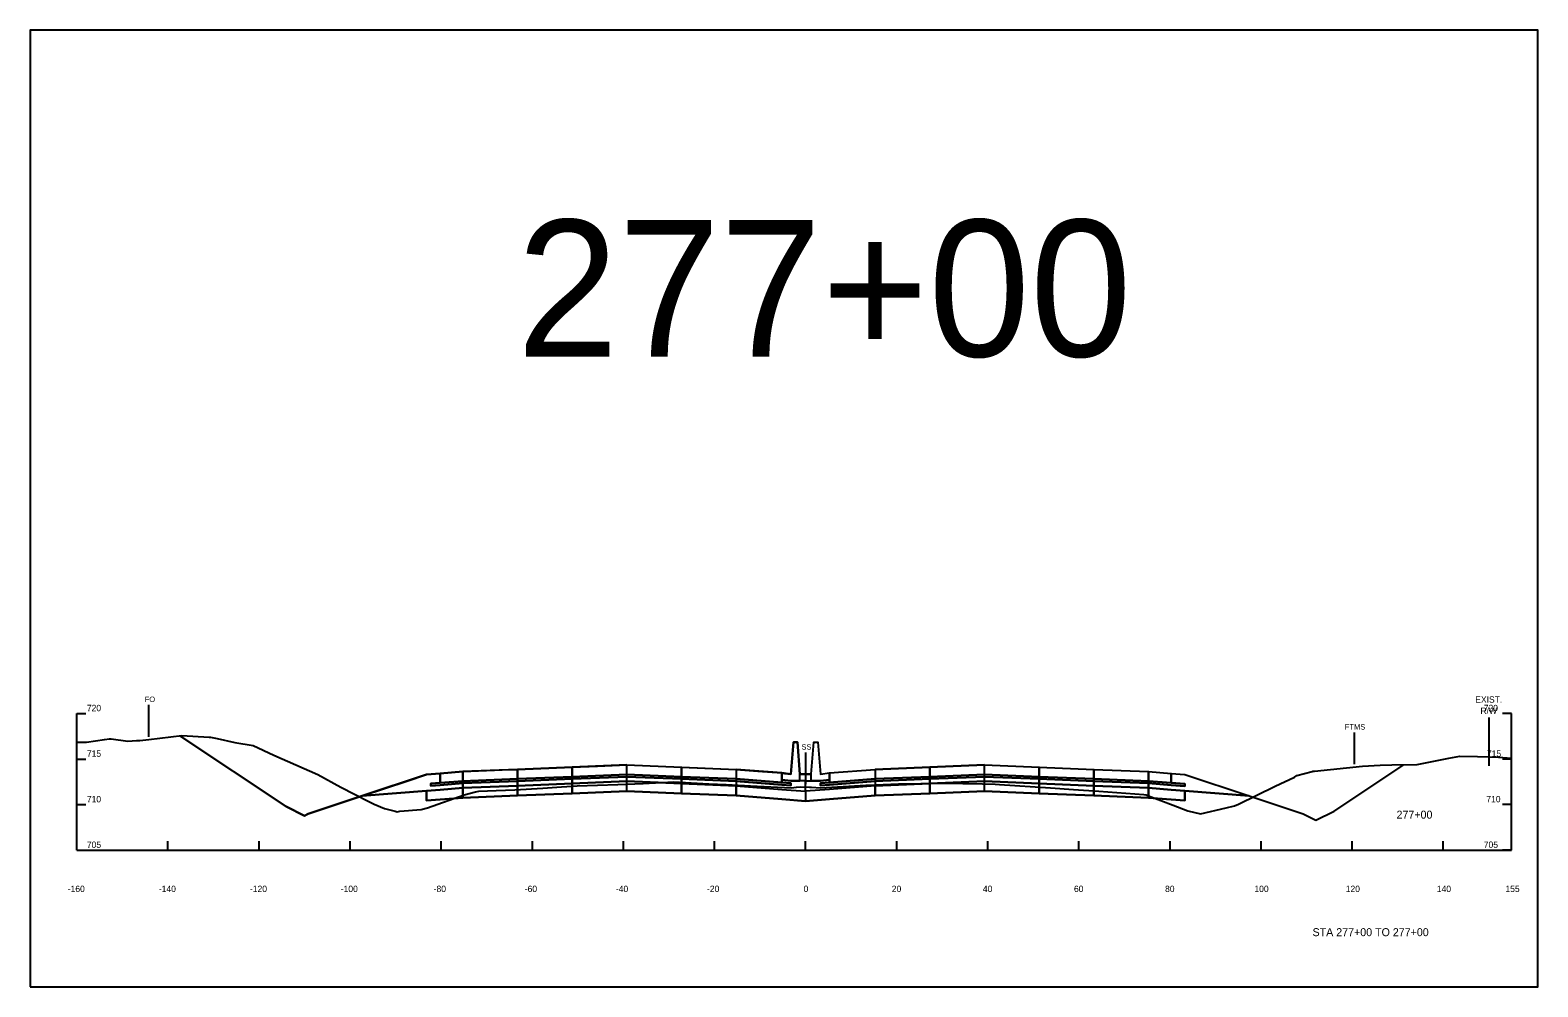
# Model space of a CAD drawing. Extents: x 0 to 2149228, y 0 to 2148913.
# Drawn here: x 2146925 to 2147256, y 2146973 to 2147183 of the extents above; entities that cross this region are included whole.
import ezdxf

# ---------------------------------------------------------------- set-up
doc = ezdxf.new("R2010")
doc.units = 0
for name, color, linetype in [('ADAMS CONST', 7, 'Continuous'), ('Default', 7, 'Continuous'), ('P_E_XS_Ground', 7, 'Continuous'), ('P_E_XS_RW', 7, 'Continuous'), ('P_E_XS_UTL', 7, 'Continuous'), ('P_MISC_TXT', 7, 'Continuous'), ('P_PROF_Grades', 7, 'Continuous'), ('P_RDWY_BarrierConc', 7, 'Continuous'), ('P_XS', 7, 'Continuous'), ('P_XS_Subgrade', 7, 'Continuous')]:
    doc.layers.add(name, color=color, linetype=linetype)

msp = doc.modelspace()

# ---------------------------------------------------------------- linework, layer by layer
at = {"layer": 'Default'}
msp.add_lwpolyline([(2146925.02, 2146973.02), (2147256.02, 2146973.02), (2147256.02, 2147183.02), (2146925.02, 2147183.02)], close=True, dxfattribs=at)
at = {"layer": 'P_E_XS_Ground'}
msp.add_lwpolyline([(2146935.27, 2147026.69), (2146937.41, 2147026.72), (2146941.32, 2147027.3), (2146942.47, 2147027.47), (2146942.82, 2147027.43), (2146946.49, 2147026.95), (2146948.37, 2147027.1), (2146949.11, 2147027.11), (2146951.07, 2147027.32), (2146958.29, 2147028.19), (2146964.35, 2147027.83), (2146964.59, 2147027.8), (2146966.04, 2147027.53), (2146969.93, 2147026.67), (2146973.99, 2147025.96), (2146978.53, 2147023.85), (2146988.17, 2147019.63), (2146993.25, 2147016.82), (2146999.38, 2147013.7), (2147000.52, 2147013.15), (2147002.84, 2147012.19), (2147005.19, 2147011.56), (2147005.59, 2147011.42), (2147006.16, 2147011.55), (2147010.86, 2147011.91), (2147012.28, 2147012.33), (2147020.33, 2147015.14), (2147022.76, 2147015.82), (2147023.55, 2147015.95), (2147027.31, 2147016.1), (2147031.4, 2147016.27), (2147037.55, 2147016.65), (2147041.69, 2147016.95), (2147045.11, 2147017.12), (2147054.06, 2147017.43), (2147059.57, 2147017.63), (2147066.31, 2147018), (2147074.01, 2147017.61), (2147077.8, 2147017.42), (2147083.2, 2147017.14), (2147092.11, 2147016.68), (2147093.25, 2147016.85), (2147094.15, 2147016.92), (2147096.11, 2147016.85), (2147096.45, 2147016.84), (2147096.58, 2147016.84), (2147098.51, 2147016.71), (2147108.5, 2147017.26), (2147112.29, 2147017.46), (2147115.66, 2147017.56), (2147125.46, 2147017.7), (2147134.11, 2147017.57), (2147136.87, 2147017.52), (2147137.84, 2147017.46), (2147149.04, 2147016.72), (2147154.06, 2147016.3), (2147159.63, 2147015.94), (2147169.51, 2147015.21), (2147170.02, 2147015.17), (2147170.51, 2147014.97), (2147175.96, 2147012.88), (2147179.21, 2147011.67), (2147181.97, 2147010.96), (2147187.56, 2147012.32), (2147189.39, 2147012.75), (2147190.28, 2147013.09), (2147198.33, 2147017.08), (2147202.56, 2147019.04), (2147203.12, 2147019.4), (2147206.45, 2147020.29), (2147206.64, 2147020.34), (2147206.97, 2147020.37), (2147217.55, 2147021.46), (2147221.42, 2147021.7), (2147223.98, 2147021.74), (2147229.52, 2147021.82), (2147236.45, 2147023.2), (2147238.9, 2147023.67), (2147242.75, 2147023.56), (2147247.41, 2147023.44), (2147250.27, 2147023.23)], dxfattribs=at)
at = {"layer": 'P_E_XS_RW'}
msp.add_line((2147245.27, 2147032.16), (2147245.27, 2147021.5), dxfattribs=at)
at = {"layer": 'P_E_XS_UTL'}
for p, q in [((2146951.09, 2147027.93), (2146951.09, 2147034.93)), ((2147215.76, 2147021.88), (2147215.76, 2147028.88)), ((2147095.29, 2147017.48), (2147095.29, 2147024.48))]:
    msp.add_line(p, q, dxfattribs=at)
at = {"layer": 'P_RDWY_BarrierConc'}
for p, q in [((2146935.27, 2147003.02), (2146935.27, 2147033.02)), ((2146935.27, 2147033.02), (2146937.27, 2147033.02)), ((2147250.27, 2147033.02), (2147248.27, 2147033.02)), ((2147250.27, 2147003.02), (2147250.27, 2147033.02)), ((2146935.27, 2147023.02), (2146937.27, 2147023.02)), ((2147250.27, 2147023.02), (2147248.27, 2147023.02)), ((2146935.27, 2147013.02), (2146937.27, 2147013.02)), ((2147250.27, 2147013.02), (2147248.27, 2147013.02)), ((2146935.27, 2147003.02), (2146935.27, 2147005.02)), ((2146935.27, 2147003.02), (2146937.27, 2147003.02)), ((2146935.27, 2147003.02), (2147250.27, 2147003.02)), ((2146955.27, 2147003.02), (2146955.27, 2147005.02)), ((2146975.27, 2147003.02), (2146975.27, 2147005.02)), ((2146995.27, 2147003.02), (2146995.27, 2147005.02)), ((2147015.27, 2147003.02), (2147015.27, 2147005.02)), ((2147035.27, 2147003.02), (2147035.27, 2147005.02)), ((2147055.27, 2147003.02), (2147055.27, 2147005.02)), ((2147075.27, 2147003.02), (2147075.27, 2147005.02)), ((2147095.27, 2147003.02), (2147095.27, 2147005.02)), ((2147115.27, 2147003.02), (2147115.27, 2147005.02)), ((2147135.27, 2147003.02), (2147135.27, 2147005.02)), ((2147155.27, 2147003.02), (2147155.27, 2147005.02)), ((2147175.27, 2147003.02), (2147175.27, 2147005.02)), ((2147195.27, 2147003.02), (2147195.27, 2147005.02)), ((2147215.27, 2147003.02), (2147215.27, 2147005.02)), ((2147235.27, 2147003.02), (2147235.27, 2147005.02)), ((2147250.27, 2147003.02), (2147248.27, 2147003.02)), ((2147250.27, 2147003.02), (2147250.27, 2147005.02))]:
    msp.add_line(p, q, dxfattribs=at)
at = {"layer": 'P_XS'}
for points in [[(2146957.91, 2147028.15), (2146981.25, 2147012.59), (2146981.38, 2147012.52), (2146985.25, 2147010.59), (2146985.63, 2147010.78), (2146986.02, 2147010.97), (2146993.32, 2147013.41), (2146997.88, 2147014.92), (2147007.71, 2147018.2), (2147012.02, 2147019.64), (2147015.02, 2147019.88), (2147020.02, 2147020.28), (2147030.4, 2147020.69), (2147032.02, 2147020.76), (2147044.02, 2147021.24), (2147049.6, 2147021.46), (2147056.02, 2147021.72), (2147068.02, 2147021.24), (2147071.5, 2147021.1), (2147080.02, 2147020.76), (2147084.74, 2147020.38), (2147090.02, 2147019.96), (2147090.65, 2147019.88), (2147092.02, 2147019.71), (2147092.58, 2147026.71), (2147093.46, 2147026.71), (2147094.02, 2147019.71), (2147095.27, 2147019.71)], [(2147095.27, 2147019.71), (2147096.52, 2147019.71), (2147097.08, 2147026.71), (2147097.96, 2147026.71), (2147098.52, 2147019.71), (2147100.52, 2147019.96), (2147110.52, 2147020.76), (2147122.52, 2147021.24), (2147134.52, 2147021.72), (2147146.52, 2147021.24), (2147158.52, 2147020.76), (2147170.52, 2147020.28), (2147175.52, 2147019.88), (2147178.52, 2147019.64), (2147192.66, 2147014.92), (2147204.52, 2147010.97), (2147207.29, 2147009.59), (2147211.29, 2147011.59), (2147226.58, 2147021.78)], [(2147095.27, 2147019.71), (2147094.02, 2147019.71), (2147095.27, 2147019.71)], [(2147095.27, 2147019.71), (2147096.52, 2147019.71), (2147095.27, 2147019.71)]]:
    msp.add_lwpolyline(points, dxfattribs=at)
for points in [[(2147094.02, 2147019.71), (2147093.46, 2147026.71), (2147092.58, 2147026.71), (2147092.02, 2147019.71), (2147090.02, 2147019.96), (2147090.02, 2147018.46), (2147092.02, 2147018.21), (2147094.02, 2147018.21)], [(2147096.52, 2147019.71), (2147097.08, 2147026.71), (2147097.96, 2147026.71), (2147098.52, 2147019.71), (2147100.52, 2147019.96), (2147100.52, 2147018.46), (2147098.52, 2147018.21), (2147096.52, 2147018.21)], [(2147056.02, 2147021.72), (2147044.02, 2147021.24), (2147044.02, 2147019.15), (2147056.02, 2147019.63)], [(2147056.02, 2147021.72), (2147068.02, 2147021.24), (2147068.02, 2147019.15), (2147056.02, 2147019.63)], [(2147134.52, 2147021.72), (2147122.52, 2147021.24), (2147122.52, 2147019.15), (2147134.52, 2147019.63)], [(2147134.52, 2147021.72), (2147146.52, 2147021.24), (2147146.52, 2147019.15), (2147134.52, 2147019.63)], [(2147020.02, 2147017.69), (2147015.02, 2147017.29), (2147013.02, 2147017.13), (2147013.02, 2147017.63), (2147015.02, 2147017.79), (2147015.02, 2147019.88), (2147012.02, 2147019.64), (2146997.88, 2147014.92), (2147012.02, 2147016.05), (2147015.02, 2147016.29), (2147020.02, 2147016.69)], [(2147020.02, 2147020.28), (2147015.02, 2147019.88), (2147015.02, 2147017.79), (2147020.02, 2147018.19)], [(2147032.02, 2147020.76), (2147020.02, 2147020.28), (2147020.02, 2147018.19), (2147032.02, 2147018.67)], [(2147032.02, 2147018.67), (2147020.02, 2147018.19), (2147020.02, 2147017.69), (2147032.02, 2147018.17)], [(2147044.02, 2147021.24), (2147032.02, 2147020.76), (2147032.02, 2147018.67), (2147044.02, 2147019.15)], [(2147044.02, 2147019.15), (2147032.02, 2147018.67), (2147032.02, 2147018.17), (2147044.02, 2147018.65)], [(2147044.02, 2147018.65), (2147032.02, 2147018.17), (2147032.02, 2147017.17), (2147044.02, 2147017.65)], [(2147056.02, 2147019.63), (2147044.02, 2147019.15), (2147044.02, 2147018.65), (2147056.02, 2147019.13)], [(2147056.02, 2147019.13), (2147044.02, 2147018.65), (2147044.02, 2147017.65), (2147056.02, 2147018.13)], [(2147056.02, 2147019.63), (2147068.02, 2147019.15), (2147068.02, 2147018.65), (2147056.02, 2147019.13)], [(2147056.02, 2147019.13), (2147068.02, 2147018.65), (2147068.02, 2147017.65), (2147056.02, 2147018.13)], [(2147068.02, 2147021.24), (2147080.02, 2147020.76), (2147080.02, 2147018.67), (2147068.02, 2147019.15)], [(2147068.02, 2147019.15), (2147080.02, 2147018.67), (2147080.02, 2147018.17), (2147068.02, 2147018.65)], [(2147068.02, 2147018.65), (2147080.02, 2147018.17), (2147080.02, 2147017.17), (2147068.02, 2147017.65)], [(2147090.02, 2147017.87), (2147090.02, 2147019.96), (2147080.02, 2147020.76), (2147080.02, 2147018.67)], [(2147090.02, 2147017.37), (2147092.02, 2147017.21), (2147092.02, 2147017.71), (2147090.02, 2147017.87), (2147080.02, 2147018.67), (2147080.02, 2147018.17)], [(2147090.02, 2147017.37), (2147080.02, 2147018.17), (2147080.02, 2147017.17), (2147090.02, 2147016.37), (2147095.27, 2147015.95), (2147095.27, 2147018.21), (2147092.02, 2147018.21), (2147090.02, 2147018.46), (2147090.02, 2147017.87), (2147092.02, 2147017.71), (2147092.02, 2147017.21)], [(2147100.52, 2147017.37), (2147110.52, 2147018.17), (2147110.52, 2147017.17), (2147100.52, 2147016.37), (2147095.27, 2147015.95), (2147095.27, 2147018.21), (2147098.52, 2147018.21), (2147100.52, 2147018.46), (2147100.52, 2147017.87), (2147098.52, 2147017.71), (2147098.52, 2147017.21)], [(2147100.52, 2147017.37), (2147098.52, 2147017.21), (2147098.52, 2147017.71), (2147100.52, 2147017.87), (2147110.52, 2147018.67), (2147110.52, 2147018.17)], [(2147100.52, 2147017.87), (2147100.52, 2147019.96), (2147110.52, 2147020.76), (2147110.52, 2147018.67)], [(2147122.52, 2147021.24), (2147110.52, 2147020.76), (2147110.52, 2147018.67), (2147122.52, 2147019.15)], [(2147122.52, 2147019.15), (2147110.52, 2147018.67), (2147110.52, 2147018.17), (2147122.52, 2147018.65)], [(2147122.52, 2147018.65), (2147110.52, 2147018.17), (2147110.52, 2147017.17), (2147122.52, 2147017.65)], [(2147134.52, 2147019.63), (2147122.52, 2147019.15), (2147122.52, 2147018.65), (2147134.52, 2147019.13)], [(2147134.52, 2147019.13), (2147122.52, 2147018.65), (2147122.52, 2147017.65), (2147134.52, 2147018.13)], [(2147134.52, 2147019.63), (2147146.52, 2147019.15), (2147146.52, 2147018.65), (2147134.52, 2147019.13)], [(2147134.52, 2147019.13), (2147146.52, 2147018.65), (2147146.52, 2147017.65), (2147134.52, 2147018.13)], [(2147146.52, 2147021.24), (2147158.52, 2147020.76), (2147158.52, 2147018.67), (2147146.52, 2147019.15)], [(2147146.52, 2147019.15), (2147158.52, 2147018.67), (2147158.52, 2147018.17), (2147146.52, 2147018.65)], [(2147146.52, 2147018.65), (2147158.52, 2147018.17), (2147158.52, 2147017.17), (2147146.52, 2147017.65)], [(2147158.52, 2147020.76), (2147170.52, 2147020.28), (2147170.52, 2147018.19), (2147158.52, 2147018.67)], [(2147158.52, 2147018.67), (2147170.52, 2147018.19), (2147170.52, 2147017.69), (2147158.52, 2147018.17)], [(2147170.52, 2147020.28), (2147175.52, 2147019.88), (2147175.52, 2147017.79), (2147170.52, 2147018.19)], [(2147170.52, 2147017.69), (2147175.52, 2147017.29), (2147178.52, 2147017.05), (2147178.52, 2147017.55), (2147175.52, 2147017.79), (2147175.52, 2147019.88), (2147178.52, 2147019.64), (2147192.66, 2147014.92), (2147178.52, 2147016.05), (2147175.52, 2147016.29), (2147170.52, 2147016.69)], [(2147020.02, 2147016.69), (2147015.02, 2147016.29), (2147012.02, 2147016.05), (2147012.02, 2147013.89), (2147015.02, 2147014.13), (2147020.02, 2147014.53)], [(2147020.02, 2147018.19), (2147015.02, 2147017.79), (2147013.02, 2147017.63), (2147013.02, 2147017.13), (2147015.02, 2147017.29), (2147020.02, 2147017.69)], [(2147032.02, 2147018.17), (2147020.02, 2147017.69), (2147020.02, 2147016.69), (2147032.02, 2147017.17)], [(2147032.02, 2147017.17), (2147020.02, 2147016.69), (2147020.02, 2147014.53), (2147032.02, 2147015.01)], [(2147044.02, 2147017.65), (2147032.02, 2147017.17), (2147032.02, 2147015.01), (2147044.02, 2147015.49)], [(2147056.02, 2147018.13), (2147044.02, 2147017.65), (2147044.02, 2147015.49), (2147056.02, 2147015.97)], [(2147056.02, 2147018.13), (2147068.02, 2147017.65), (2147068.02, 2147015.49), (2147056.02, 2147015.97)], [(2147080.02, 2147015.01), (2147068.02, 2147015.49), (2147068.02, 2147017.65), (2147080.02, 2147017.17)], [(2147080.02, 2147017.17), (2147090.02, 2147016.37), (2147095.27, 2147015.95), (2147095.27, 2147013.79), (2147090.02, 2147014.21), (2147080.02, 2147015.01)], [(2147110.52, 2147017.17), (2147100.52, 2147016.37), (2147095.27, 2147015.95), (2147095.27, 2147013.79), (2147100.52, 2147014.21), (2147110.52, 2147015.01)], [(2147122.52, 2147017.65), (2147110.52, 2147017.17), (2147110.52, 2147015.01), (2147122.52, 2147015.49)], [(2147134.52, 2147018.13), (2147122.52, 2147017.65), (2147122.52, 2147015.49), (2147134.52, 2147015.97)], [(2147134.52, 2147018.13), (2147146.52, 2147017.65), (2147146.52, 2147015.49), (2147134.52, 2147015.97)], [(2147146.52, 2147017.65), (2147158.52, 2147017.17), (2147158.52, 2147015.01), (2147146.52, 2147015.49)], [(2147158.52, 2147018.17), (2147170.52, 2147017.69), (2147170.52, 2147016.69), (2147158.52, 2147017.17)], [(2147158.52, 2147017.17), (2147170.52, 2147016.69), (2147170.52, 2147014.53), (2147158.52, 2147015.01)], [(2147170.52, 2147018.19), (2147175.52, 2147017.79), (2147178.52, 2147017.55), (2147178.52, 2147017.05), (2147175.52, 2147017.29), (2147170.52, 2147017.69)], [(2147170.52, 2147016.69), (2147175.52, 2147016.29), (2147178.52, 2147016.05), (2147178.52, 2147013.89), (2147175.52, 2147014.13), (2147170.52, 2147014.53)]]:
    msp.add_lwpolyline(points, close=True, dxfattribs=at)
at = {"layer": 'P_XS_Subgrade'}
for points in [[(2146981.25, 2147012.59), (2146957.91, 2147028.15)], [(2147211.29, 2147011.59), (2147226.58, 2147021.78)], [(2147032.02, 2147015.01), (2147020.02, 2147014.53), (2147015.02, 2147014.13), (2147012.02, 2147013.89), (2147012.02, 2147016.05), (2146997.88, 2147014.92), (2147012.02, 2147016.05), (2147012.02, 2147013.89), (2147015.02, 2147014.13)], [(2147044.02, 2147015.49), (2147032.02, 2147015.01), (2147020.02, 2147014.53)], [(2147056.02, 2147015.97), (2147044.02, 2147015.49)], [(2147056.02, 2147015.97), (2147068.02, 2147015.49), (2147056.02, 2147015.97)], [(2147068.02, 2147015.49), (2147080.02, 2147015.01), (2147068.02, 2147015.49)], [(2147122.52, 2147015.49), (2147110.52, 2147015.01), (2147122.52, 2147015.49)], [(2147134.52, 2147015.97), (2147122.52, 2147015.49), (2147134.52, 2147015.97)], [(2147134.52, 2147015.97), (2147146.52, 2147015.49)], [(2147146.52, 2147015.49), (2147158.52, 2147015.01), (2147146.52, 2147015.49)], [(2147158.52, 2147015.01), (2147170.52, 2147014.53), (2147175.52, 2147014.13), (2147178.52, 2147013.89), (2147178.52, 2147016.05), (2147192.66, 2147014.92)], [(2146985.25, 2147010.59), (2146981.25, 2147012.59)], [(2146997.88, 2147014.92), (2146986.02, 2147010.97), (2146985.25, 2147010.59)], [(2147192.66, 2147014.92), (2147204.52, 2147010.97), (2147207.29, 2147009.59)], [(2147207.29, 2147009.59), (2147211.29, 2147011.59)]]:
    msp.add_lwpolyline(points, dxfattribs=at)
for points in [[(2147080.02, 2147015.01), (2147090.02, 2147014.21), (2147095.27, 2147013.79), (2147090.02, 2147014.21)], [(2147100.52, 2147014.21), (2147110.52, 2147015.01), (2147100.52, 2147014.21), (2147095.27, 2147013.79)]]:
    msp.add_lwpolyline(points, close=True, dxfattribs=at)

# ---------------------------------------------------------------- texts
at = {"layer": 'ADAMS CONST'}
msp.add_text('277+00', height=30, dxfattribs=at).set_placement((2147031.86, 2147111.37))
at = {"layer": 'Default'}
for p in [(2146957.87, 2147028.1), (2147226.55, 2147021.73), (2146997.85, 2147014.87), (2147031.99, 2147014.96), (2147055.99, 2147015.92), (2147079.99, 2147014.96), (2147110.49, 2147014.96), (2147134.49, 2147015.92), (2147192.63, 2147014.87), (2146981.22, 2147012.54), (2147011.99, 2147013.84), (2147095.24, 2147013.74), (2147095.24, 2147013.74), (2147100.49, 2147014.16), (2147170.49, 2147014.48), (2147178.49, 2147013.84), (2146985.22, 2147010.54), (2146985.99, 2147010.92), (2147204.49, 2147010.92), (2147207.26, 2147009.54), (2147211.26, 2147011.54)]:
    msp.add_text('+', height=0.1, dxfattribs=at).set_placement(p)
at = {"layer": 'P_E_XS_RW'}
for s, p in [('EXIST.', (2147242.28, 2147035.38)), ('R/W', (2147243.41, 2147032.93))]:
    msp.add_text(s, height=1.4, rotation=360, dxfattribs=at).set_placement(p)
at = {"layer": 'P_E_XS_UTL'}
for s, p in [('FO', (2146950.16, 2147035.53)), ('FTMS', (2147213.63, 2147029.48)), ('SS', (2147094.35, 2147025.08))]:
    msp.add_text(s, height=1.2, rotation=360, dxfattribs=at).set_placement(p)
at = {"layer": 'P_MISC_TXT'}
for s, p in [('277+00', (2147225, 2147009.94)), ('STA 277+00 TO 277+00', (2147206.56, 2146984.14))]:
    msp.add_text(s, height=1.75, dxfattribs=at).set_placement(p)
at = {"layer": 'P_PROF_Grades'}
for s, p in [('720', (2146937.47, 2147033.52)), ('720', (2147244.14, 2147033.52)), ('715', (2146937.47, 2147023.52)), ('715', (2147244.84, 2147023.52)), ('710', (2146937.47, 2147013.52)), ('710', (2147244.71, 2147013.52)), ('705', (2146937.47, 2147003.52)), ('705', (2147244.15, 2147003.52)), ('-160', (2146933.27, 2146993.82)), ('-140', (2146953.27, 2146993.82)), ('-120', (2146973.27, 2146993.82)), ('-100', (2146993.21, 2146993.82)), ('-80', (2147013.61, 2146993.82)), ('-60', (2147033.61, 2146993.82)), ('-40', (2147053.61, 2146993.82)), ('-20', (2147073.61, 2146993.82)), ('0', (2147094.81, 2146993.82)), ('20', (2147114.18, 2146993.82)), ('40', (2147134.18, 2146993.82)), ('60', (2147154.18, 2146993.82)), ('80', (2147174.18, 2146993.82)), ('100', (2147193.79, 2146993.82)), ('120', (2147213.84, 2146993.82)), ('140', (2147233.84, 2146993.82)), ('155', (2147248.9, 2146993.82))]:
    msp.add_text(s, height=1.4, dxfattribs=at).set_placement(p)
at = {"layer": 'P_RDWY_BarrierConc'}
msp.add_text('-', height=0.0001, dxfattribs=at).set_placement((2146935.27, 2147003.02))

doc.saveas('drawing.dxf')
